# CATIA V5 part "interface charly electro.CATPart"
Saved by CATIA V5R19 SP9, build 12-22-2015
Part number: interface charly electro
Bounding box of the stored display mesh (mm): x -200 to 200, y -123.5 to 123.5, z 0 to 19
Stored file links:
  Z:\fausse table rondelle-20220905T211342Z-001\fausse table rondelle\interface charly electro.CATPart
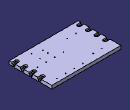
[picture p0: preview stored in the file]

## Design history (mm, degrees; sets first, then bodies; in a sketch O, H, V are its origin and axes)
AxisSystem1: origin (0, 0, 0), X (1, 0, 0), Y (0, 1, 0), Z (0, 0, 1)
Body1 (main body)
  Sketch1 on XY plane of AxisSystem1, origin (0, 0, 0), H (1, 0, 0), V (0, 1, 0)
    line L1 (200, 123.5) -> (200, -123.5)
    line L2 (200, -123.5) -> (-200, -123.5)
    line L3 (-200, -123.5) -> (-200, 123.5)
    line L4 (-200, 123.5) -> (200, 123.5)
    length L4 = 400
    length L1 = 247
    vertical: L1 V, L3 V
    horizontal: L2 H, L4 H
    equidistance: L1 L3 O, L2 L4 O
  Pad1: profile Sketch1, direction (0, 0, 1), length 19
  Sketch2 on start face of Pad1, origin (131.1733, -56.2905, 0), H (1, 0, 0), V (0, 1, 0)
    point P1 (-261.1733, 139.7905)
    reference intersected line E1 (-331.1733, 179.7905) -> (68.8267, 179.7905) from face of Pad1 from Sketch1.L4
    reference intersected line E2 (-331.1733, -67.2095) -> (-331.1733, 179.7905) from face of Pad1 from Sketch1.L3
    distance P1 E2 = 70
    distance P1 E1 = 40
  Hole1: placed by Sketch2, at (-130, 83.5, 0) direction (0, 0, 1), diameter 5, through (limit type 6), counterbore diameter 15, counterbore depth 15
  RectPattern1: of Hole1, direction 1 instances 2, spacing 50, along X axis, direction 2 instances 2, spacing 150, along Y axis reversed
  Sketch3 on start face of Pad1, origin (-179.7372, 103.0284, 0), H (1, 0, 0), V (0, 1, 0)
    point P1 (329.7372, 0.4716)
    reference intersected line E1 (-20.2628, 20.4716) -> (379.7372, 20.4716) from face of Pad1 from Sketch1.L4
    reference intersected line E2 (379.7372, 20.4716) -> (379.7372, -226.5284) from face of Pad1 from Sketch1.L1
    distance P1 E2 = 50
    distance P1 E1 = 20
  Hole2: placed by Sketch3, at (150, 103.5, 0) direction (0, 0, 1), diameter 5, through (limit type 6), counterbore diameter 15, counterbore depth 15
  RectPattern2: of Hole2, direction 1 instances 2, spacing 113, along Y axis reversed, direction 2 instances 4, spacing 50, along X axis reversed
  Sketch4 on start face of Pad1, origin (106.3433, -47.4661, 0), H (1, 0, 0), V (0, -1, 0)
    point P1 (-6.3433, 46.0339)
    reference intersected line E1 (93.6567, 76.0339) -> (93.6567, -170.9661) from face of Pad1 from Sketch1.L1
    reference intersected line E2 (-306.3433, 76.0339) -> (93.6567, 76.0339) from face of Pad1 from Sketch1.L2
    distance P1 E1 = 100
    distance P1 E2 = 30
  Hole3: placed by Sketch4, at (100, -93.5, 0) direction (0, 0, 1), diameter 5, through (limit type 6), counterbore diameter 15, counterbore depth 15
  Sketch5 on start face of Pad1, origin (155.7389, -35.6399, 0), H (1, 0, 0), V (0, -1, 0)
    point P1 (-55.7389, 9.8601)
    reference projected point E1 (-55.7389, 57.8601) from axis of face of Hole3
    reference projected point E2 (-55.7389, 57.8601) from axis of face of Hole3
    distance P1 E1 = 48
    distance P1 E2 H = 0
  Hole4: placed by Sketch5, at (100, -45.5, 0) direction (0, 0, 1), diameter 5, through (limit type 6), counterbore diameter 15, counterbore depth 15
  Sketch6 on start face of Pad1, origin (104.8923, -58.437, 0), H (1, 0, 0), V (0, -1, 0)
    point P1 (-55.3923, 19.563)
    reference projected point E1 (-4.8923, 35.063) from axis of face of Hole3
    reference projected point E2 (-4.8923, 35.063) from axis of face of Hole3
    distance E1 P1 H = 50.5
    distance E2 P1 V = 15.5
  Hole5: placed by Sketch6, at (49.5, -78, 0) direction (0, 0, 1), diameter 5, through (limit type 6), counterbore diameter 15, counterbore depth 15
  Sketch7 on start face of Pad1, origin (103.7745, -32.7621, 0), H (1, 0, 0), V (0, -1, 0)
    point P1 (-54.2745, 17.2379)
    reference projected point E1 (-3.7745, 60.7379) from axis of face of Hole3
    reference projected point E2 (-3.7745, 60.7379) from axis of face of Hole3
    distance E1 P1 H = 50.5
    distance E2 P1 V = 43.5
  Hole6: placed by Sketch7, at (49.5, -50, 0) direction (0, 0, 1), diameter 5, through (limit type 6), counterbore diameter 15, counterbore depth 15
  Sketch8 on end face of Pad1, origin (0, 0, 19), H (1, 0, 0), V (0, 1, 0)
    construction line L1 (-220, -98.5) -> (-180, -98.5)
    point P1 (-220, -98.5)
    point P2 (-180, -98.5)
    line L2 (-220, -94.5) -> (-180, -94.5)
    line L3 (-180, -102.5) -> (-220, -102.5)
    arc A1 centre (-180, -98.5) radius 4 from (-180, -94.5) to (-180, -102.5) cw
    arc A2 centre (-220, -98.5) radius 4 from (-220, -102.5) to (-220, -94.5) cw
    reference intersected line E1 (-200, -123.5) -> (-200, 123.5) from face of Pad1 from Sketch1.L3
    reference intersected line E2 (200, -123.5) -> (-200, -123.5) from face of Pad1 from Sketch1.L2
    distance L1 L2 = 4
    length L1 = 40
    distance L1 E2 = 25
    horizontal: L1 H
    tangency: A1 L2, A2 L2, A1 L3, A2 L3
    symmetry: P2 P1 E1
  Pocket1: profile Sketch8, direction (0, 0, -1), length 19
  Sketch9 on end face of Pad1, origin (0, 0, 19), H (1, 0, 0), V (0, 1, 0)
    construction line L1 (-220, -98.5) -> (-180, -98.5)
    point P2 (-180, -98.5)
    line L2 (-220, -88.5) -> (-180, -88.5)
    line L3 (-180, -108.5) -> (-220, -108.5)
    arc A1 centre (-180, -98.5) radius 10 from (-180, -88.5) to (-180, -108.5) cw
    arc A2 centre (-220, -98.5) radius 10 from (-220, -108.5) to (-220, -88.5) cw
    reference projected point E1 (-180, -98.5) from axis of face of Pocket1 from Sketch8.A1
    distance L1 L2 = 10
    length L1 = 40
    horizontal: L1 H
    tangency: A1 L2, A2 L2, A1 L3, A2 L3
    coincidence: P2 E1
  Pocket2: profile Sketch9, direction (0, 0, -1), length 9
  RectPattern3: of Pocket1, Pocket2, direction 1 instances 4, spacing 50, along Y axis, direction 2 instances 2, spacing 400, along X axis
  DatumCurve1 to DatumCurve3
